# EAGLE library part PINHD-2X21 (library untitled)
PIN HEADER
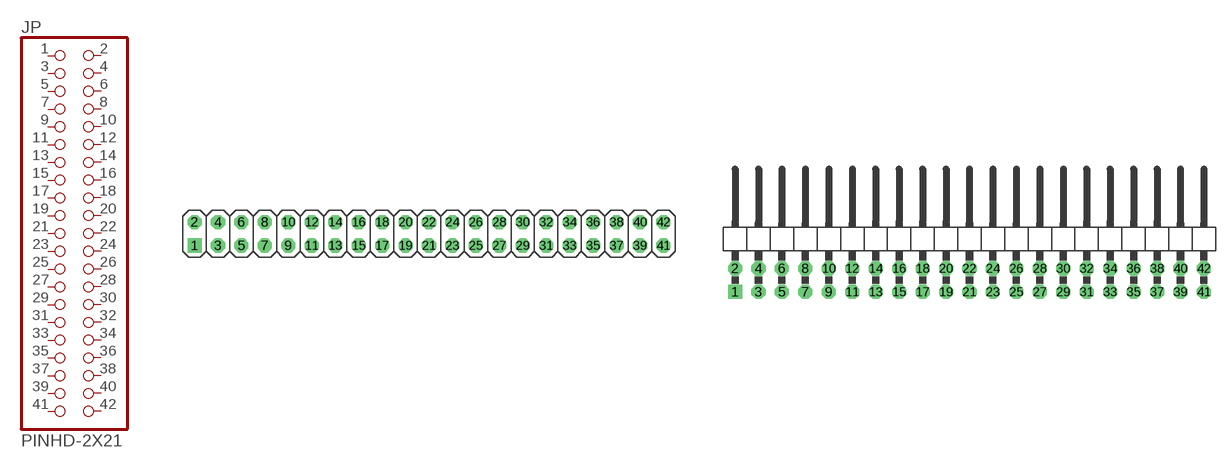
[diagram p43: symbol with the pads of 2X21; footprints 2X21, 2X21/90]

Designator prefix JP

## PINHD-2X21_2.54  [2X21]
1  1  pas
2  2  pas
3  3  pas
4  4  pas
5  5  pas
6  6  pas
7  7  pas
8  8  pas
9  9  pas
10  10  pas
11  11  pas
12  12  pas
13  13  pas
14  14  pas
15  15  pas
16  16  pas
17  17  pas
18  18  pas
19  19  pas
20  20  pas
21  21  pas
22  22  pas
23  23  pas
24  24  pas
25  25  pas
26  26  pas
27  27  pas
28  28  pas
29  29  pas
30  30  pas
31  31  pas
32  32  pas
33  33  pas
34  34  pas
35  35  pas
36  36  pas
37  37  pas
38  38  pas
39  39  pas
40  40  pas
41  41  pas
42  42  pas

## PINHD-2X21_2.54-90°  [2X21/90]
Pads as for 2X21

## PINHD-2X21_2.00  [2X21M]
Pads as for 2X21

## PINHD-2X21_2.54-SMD  [2X21SMD]
Pads as for 2X21

## PINHD-2X21_2.54-SMD-90°  [2X21SMD/90]
Pads as for 2X21

## Footprint 2X21 (pad centres in mm)
PIN HEADER - 2.54
drill 1.016 square: 1 -24.13,-1.27
drill 1.016 octagon: 2 -24.13,1.27; 3 -21.59,-1.27; 4 -21.59,1.27; 5 -19.05,-1.27; 6 -19.05,1.27; 7 -16.51,-1.27; 8 -16.51,1.27; 9 -13.97,-1.27; 10 -13.97,1.27; 11 -11.43,-1.27; 12 -11.43,1.27; 13 -8.89,-1.27; 14 -8.89,1.27; 15 -6.35,-1.27; 16 -6.35,1.27; 17 -3.81,-1.27; 18 -3.81,1.27; 19 -1.27,-1.27; 20 -1.27,1.27; 21 1.27,-1.27; 22 1.27,1.27; 23 3.81,-1.27; 24 3.81,1.27; 25 6.35,-1.27; 26 6.35,1.27; 27 8.89,-1.27; 28 8.89,1.27; 29 11.43,-1.27; 30 11.43,1.27; 31 13.97,-1.27; 32 13.97,1.27; 33 16.51,-1.27; 34 16.51,1.27; 35 19.05,-1.27; 36 19.05,1.27; 37 21.59,-1.27; 38 21.59,1.27; 39 24.13,-1.27; 40 24.13,1.27; 41 26.67,-1.27; 42 26.67,1.27

## Footprint 2X21/90 (pad centres in mm)
PIN HEADER - 2.54 90°
drill 1.016 square: 1 -24.13,-6.35
drill 1.016 octagon: 2 -24.13,-3.81; 3 -21.59,-6.35; 4 -21.59,-3.81; 5 -19.05,-6.35; 6 -19.05,-3.81; 7 -16.51,-6.35; 8 -16.51,-3.81; 9 -13.97,-6.35; 10 -13.97,-3.81; 11 -11.43,-6.35; 12 -11.43,-3.81; 13 -8.89,-6.35; 14 -8.89,-3.81; 15 -6.35,-6.35; 16 -6.35,-3.81; 17 -3.81,-6.35; 18 -3.81,-3.81; 19 -1.27,-6.35; 20 -1.27,-3.81; 21 1.27,-6.35; 22 1.27,-3.81; 23 3.81,-6.35; 24 3.81,-3.81; 25 6.35,-6.35; 26 6.35,-3.81; 27 8.89,-6.35; 28 8.89,-3.81; 29 11.43,-6.35; 30 11.43,-3.81; 31 13.97,-6.35; 32 13.97,-3.81; 33 16.51,-6.35; 34 16.51,-3.81; 35 19.05,-6.35; 36 19.05,-3.81; 37 21.59,-6.35; 38 21.59,-3.81; 39 24.13,-6.35; 40 24.13,-3.81; 41 26.67,-6.35; 42 26.67,-3.81

## Footprint 2X21M (pad centres in mm)
PIN HEADER - 2
drill 0.914 square: 1 -20,-1
drill 0.914 round: 2 -20,1; 3 -18,-1; 4 -18,1; 5 -16,-1; 6 -16,1; 7 -14,-1; 8 -14,1; 9 -12,-1; 10 -12,1; 11 -10,-1; 12 -10,1; 13 -8,-1; 14 -8,1; 15 -6,-1; 16 -6,1; 17 -4,-1; 18 -4,1; 19 -2,-1; 20 -2,1; 21 0,-1; 22 0,1; 23 2,-1; 24 2,1; 25 4,-1; 26 4,1; 27 6,-1; 28 6,1; 29 8,-1; 30 8,1; 31 10,-1; 32 10,1; 33 12,-1; 34 12,1; 35 14,-1; 36 14,1; 37 16,-1; 38 16,1; 39 18,-1; 40 18,1; 41 20,-1; 42 20,1

## Footprint 2X21SMD (pad centres in mm)
PIN HEADER - 2.54 SMD
smd 1.016 x 3.302: 1 -1.27,-3.81; 2 -1.27,1.27; 3 1.27,-3.81; 4 1.27,1.27; 5 3.81,-3.81; 6 3.81,1.27; 7 6.35,-3.81; 8 6.35,1.27; 9 8.89,-3.81; 10 8.89,1.27; 11 11.43,-3.81; 12 11.43,1.27; 13 13.97,-3.81; 14 13.97,1.27; 15 16.51,-3.81; 16 16.51,1.27; 17 19.05,-3.81; 18 19.05,1.27; 19 21.59,-3.81; 20 21.59,1.27; 21 24.13,-3.81; 22 24.13,1.27; 23 26.67,-3.81; 24 26.67,1.27; 25 29.21,-3.81; 26 29.21,1.27; 27 31.75,-3.81; 28 31.75,1.27; 29 34.29,-3.81; 30 34.29,1.27; 31 36.83,-3.81; 32 36.83,1.27; 33 39.37,-3.81; 34 39.37,1.27; 35 41.91,-3.81; 36 41.91,1.27; 37 44.45,-3.81; 38 44.45,1.27; 39 46.99,-3.81; 40 46.99,1.27; 41 49.53,-3.81; 42 49.53,1.27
